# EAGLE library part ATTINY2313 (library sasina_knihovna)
Procesor ATtinny2313 od firmy Atmel.
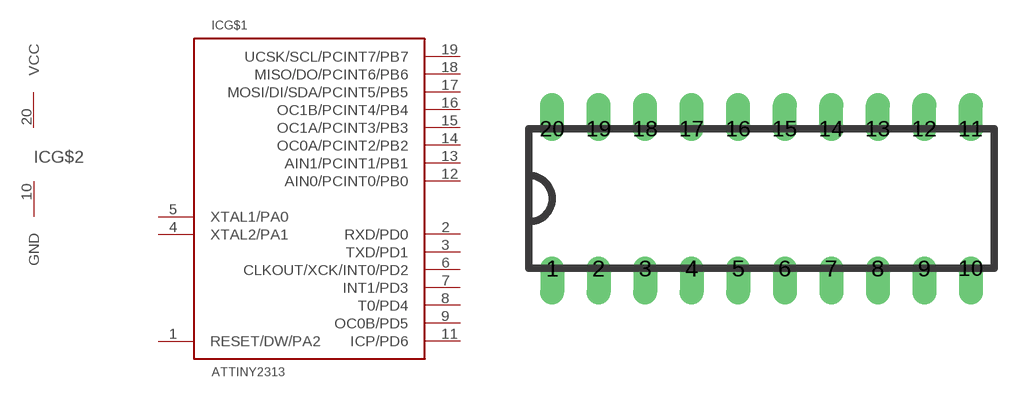
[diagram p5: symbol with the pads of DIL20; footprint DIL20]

Designator prefix IC; gates G$1=ATTINY2313 G$2=NAPAJENI

## ATTINY2313  [DIL20]
1  G$1:RESET/DW/PA2
2  G$1:RXD/PD0
3  G$1:TXD/PD1
4  G$1:XTAL2/PA1
5  G$1:XTAL1/PA0
6  G$1:CLKOUT/XCK/INT0/PD2
7  G$1:INT1/PD3
8  G$1:T0/PD4
9  G$1:OC0B/PD5
10  G$2:GND  pwr
11  G$1:ICP/PD6
12  G$1:AIN0/PCINT0/PB0
13  G$1:AIN1/PCINT1/PB1
14  G$1:OC0A/PCINT2/PB2
15  G$1:OC1A/PCINT3/PB3
16  G$1:OC1B/PCINT4/PB4
17  G$1:MOSI/DI/SDA/PCINT5/PB5
18  G$1:MISO/DO/PCINT6/PB6
19  G$1:UCSK/SCL/PCINT7/PB7
20  G$2:VCC  pwr

## Footprint DIL20 (pad centres in mm)
drill 0.8 offset: 1 -15.24,-1.27; 2 -12.7,-1.27; 3 -10.16,-1.27; 4 -7.62,-1.27; 5 -5.08,-1.27; 6 -2.54,-1.27; 7 0,-1.27; 8 2.54,-1.27; 9 5.08,-1.27; 10 7.62,-1.27; 11 7.62,6.35; 12 5.08,6.35; 13 2.54,6.35; 14 0,6.35; 15 -2.54,6.35; 16 -5.08,6.35; 17 -7.62,6.35; 18 -10.16,6.35; 19 -12.7,6.35; 20 -15.24,6.35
